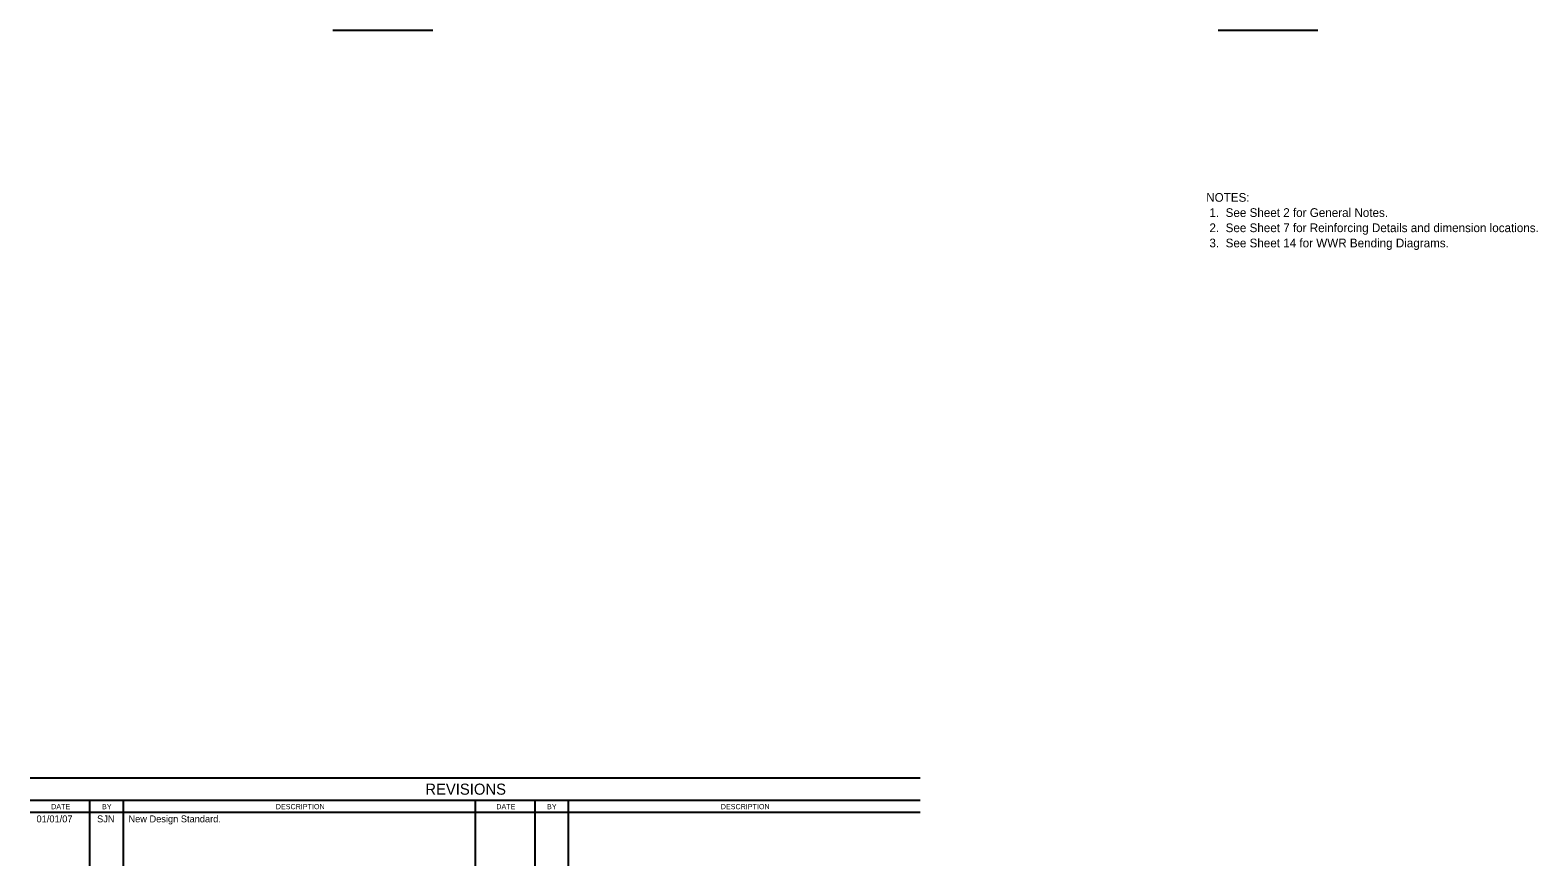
# Model space of a CAD drawing. Extents: x 10346.98 to 10349.19, y 76371.36 to 76372.62.
# Drawn here: x 10346.977 to 10348.068, y 76371.356 to 76371.961 of the extents above; entities that cross this region are included whole.
import ezdxf

# ---------------------------------------------------------------- set-up
doc = ezdxf.new("R2010")
doc.units = 0
for name, color, linetype in [('AdhocPoint_dp', 7, 'Continuous'), ('Border', 7, 'Continuous'), ('PlotBorder_dp', 7, 'Continuous')]:
    doc.layers.add(name, color=color, linetype=linetype)

msp = doc.modelspace()

# ---------------------------------------------------------------- linework, layer by layer
at = {"layer": 'Border'}
for p, q in [((10347.6212, 76371.419), (10346.9771, 76371.419)), ((10347.6212, 76371.4029), (10346.9771, 76371.4029)), ((10347.0201, 76371.4029), (10347.0201, 76371.3556)), ((10347.0443, 76371.4029), (10347.0443, 76371.3556)), ((10347.2991, 76371.4029), (10347.2991, 76371.3556)), ((10347.3422, 76371.4029), (10347.3422, 76371.3556)), ((10347.3663, 76371.4029), (10347.3663, 76371.3556)), ((10346.9771, 76371.3944), (10347.6212, 76371.3944))]:
    msp.add_line(p, q, dxfattribs=at)
at = {"layer": 'PlotBorder_dp'}
for p, q in [((10347.1962, 76371.9605), (10347.2684, 76371.9605)), ((10347.8367, 76371.9605), (10347.9089, 76371.9605))]:
    msp.add_line(p, q, dxfattribs=at)

# ---------------------------------------------------------------- texts
at = {"layer": 'AdhocPoint_dp'}
for s, height, p in [('REVISIONS', 0.00802, (10347.263, 76371.4071)), ('01/01/07', 0.005, (10346.9817, 76371.3871)), ('SJN', 0.005, (10347.0255, 76371.3871)), ('BY', 0.00375, (10347.0291, 76371.3966)), ('New Design Standard.', 0.005, (10347.0482, 76371.3871)), ('BY', 0.00375, (10347.3511, 76371.3966))]:
    msp.add_text(s, height=height, dxfattribs=at).set_placement(p)
for s, height, rotation, p in [('DATE', 0.00374, 359.8693, (10346.9923, 76371.3966)), ('DESCRIPTION', 0.003752, 0.0498, (10347.1548, 76371.3966)), ('DATE', 0.00374, 359.8693, (10347.3144, 76371.3966)), ('DESCRIPTION', 0.003752, 0.0498, (10347.4768, 76371.3966))]:
    msp.add_text(s, height=height, rotation=rotation, dxfattribs=at).set_placement(p)
at = {"layer": 'PlotBorder_dp'}
for s, p in [('NOTES:', (10347.8281, 76371.8363)), (' 1.  See Sheet 2 for General Notes.', (10347.8281, 76371.8253)), (' 2.  See Sheet 7 for Reinforcing Details and dimension locations.', (10347.8281, 76371.8143)), (' 3.  See Sheet 14 for WWR Bending Diagrams.', (10347.8281, 76371.8033))]:
    msp.add_text(s, height=0.0063, dxfattribs=at).set_placement(p)

doc.saveas('drawing.dxf')
